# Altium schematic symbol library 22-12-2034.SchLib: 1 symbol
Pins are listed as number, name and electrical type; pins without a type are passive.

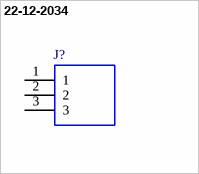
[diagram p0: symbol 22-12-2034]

## 22-12-2034
designator J?
Headers & Wire Housings R/A PCB HDR 3P GOLD FRICTION LOCK; Manufacturer_Name: Molex; Geometry.Height: 6.6mm
footprint 22122034
pins: 1, 2, 3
